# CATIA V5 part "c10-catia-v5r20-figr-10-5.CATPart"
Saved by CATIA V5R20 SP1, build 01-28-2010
Part number: Part1
Bounding box of the stored display mesh (mm): x -9.888 to 10, y -9.972 to 9.972, z 0 to 10
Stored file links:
  D:\v5_r20\psrt_files_downloaded\c10\c10-catia-v5r20-figr-10-5.CATPart
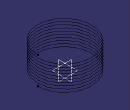
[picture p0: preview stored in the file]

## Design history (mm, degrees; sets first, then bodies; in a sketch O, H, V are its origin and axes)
Set1
  Helix1: Direction {line stored without definition}, RefPoint {point type Coord, X 10, Y 0, Z 0}, Pitch 1, Height 10, TaperAngle 0
Body1 (main body)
